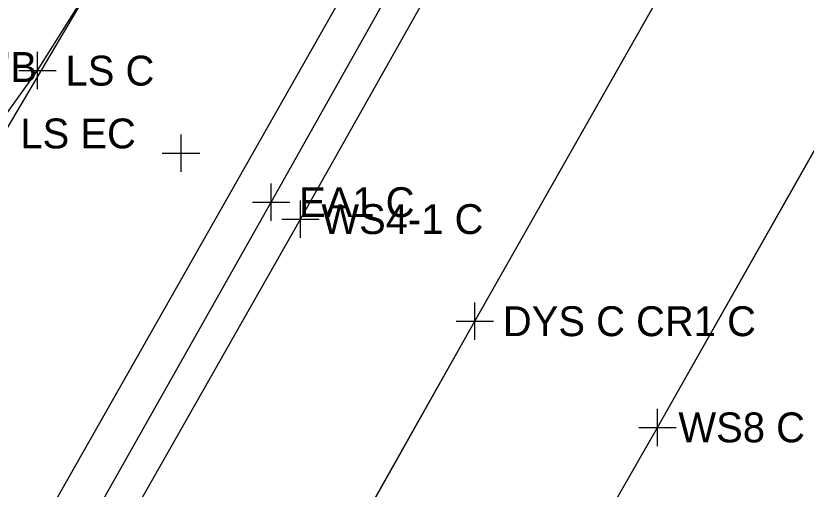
# Model space of a CAD drawing. Extents: x 1363693 to 1365209, y 422201 to 424153.
# Drawn here: x 1364063.69 to 1364106.01, y 422743.08 to 422768.44 of the extents above; entities that cross this region are included whole.
import ezdxf

# ---------------------------------------------------------------- set-up
doc = ezdxf.new("R2010")
doc.units = 0
for name, color, linetype in [('O-ALGN-BASELINE-WERK-CL-RW', 7, 'Continuous'), ('OWNERS', 7, 'Continuous'), ('PM_X_Channelizing_Line', 7, 'Continuous'), ('PM_X_CL_Double_Solid', 7, 'Continuous'), ('PM_X_Edge_Line', 7, 'Continuous'), ('SV_X_Original_Ground', 7, 'Continuous'), ('SV_X_Random_Point', 7, 'Continuous'), ('SV_X_Shot_Marker', 7, 'Continuous'), ('UT_X_FO', 7, 'Continuous'), ('UT_X_Gas', 7, 'Continuous'), ('VG_X_Flower_Bed', 7, 'Continuous'), ('VG_X_Text', 7, 'Continuous')]:
    doc.layers.add(name, color=color, linetype=linetype)

msp = doc.modelspace()

# ---------------------------------------------------------------- linework, layer by layer
at = {"layer": 'O-ALGN-BASELINE-WERK-CL-RW'}
for points in [[(1364063.861, 422708.444), (1364075.973, 422730.252), (1364088.269, 422752.078), (1364100.636, 422773.911), (1364112.961, 422795.674), (1364125.29, 422817.23)], [(1364073.278, 422703.065), (1364085.603, 422724.652), (1364098.051, 422746.39), (1364110.44, 422768.276), (1364122.785, 422790.021), (1364135.008, 422811.616)]]:
    msp.add_lwpolyline(points, dxfattribs=at)
at = {"layer": 'OWNERS'}
msp.add_lwpolyline([(1364052.728, 422714.955), (1364065.039, 422736.632), (1364077.353, 422758.456), (1364089.632, 422780.271), (1364102.08, 422801.911)], dxfattribs=at)
at = {"layer": 'PM_X_Channelizing_Line'}
for p, q in [((1364078.931, 422757.548), (1364091.221, 422779.339)), ((1364088.269, 422752.078), (1364100.636, 422773.911)), ((1364098.051, 422746.39), (1364110.44, 422768.276)), ((1364098.051, 422746.39), (1364110.44, 422768.276)), ((1364066.522, 422735.694), (1364078.931, 422757.548)), ((1364075.973, 422730.252), (1364088.269, 422752.078)), ((1364085.603, 422724.652), (1364098.051, 422746.39)), ((1364085.603, 422724.652), (1364098.051, 422746.39))]:
    msp.add_line(p, q, dxfattribs=at)
at = {"layer": 'PM_X_CL_Double_Solid'}
for p, q in [((1364088.269, 422752.078), (1364100.636, 422773.911)), ((1364075.973, 422730.252), (1364088.269, 422752.078))]:
    msp.add_line(p, q, dxfattribs=at)
at = {"layer": 'PM_X_Edge_Line'}
for p, q in [((1364078.931, 422757.548), (1364091.221, 422779.339)), ((1364066.522, 422735.694), (1364078.931, 422757.548))]:
    msp.add_line(p, q, dxfattribs=at)
at = {"layer": 'SV_X_Original_Ground'}
for p, q in [((1364072.532, 422760.084), (1364072.532, 422762.084)), ((1364071.532, 422761.084), (1364073.532, 422761.084)), ((1364078.931, 422756.548), (1364078.931, 422758.548)), ((1364077.931, 422757.548), (1364079.931, 422757.548)), ((1364088.269, 422751.078), (1364088.269, 422753.078)), ((1364087.269, 422752.078), (1364089.269, 422752.078)), ((1364098.051, 422745.39), (1364098.051, 422747.39)), ((1364097.051, 422746.39), (1364099.051, 422746.39))]:
    msp.add_line(p, q, dxfattribs=at)
at = {"layer": 'SV_X_Random_Point'}
for p, q in [((1364064.848, 422764.503), (1364064.848, 422766.503)), ((1364063.848, 422765.503), (1364065.848, 422765.503))]:
    msp.add_line(p, q, dxfattribs=at)
at = {"layer": 'SV_X_Shot_Marker'}
for p, q in [((1364077.353, 422757.456), (1364077.353, 422759.456)), ((1364076.353, 422758.456), (1364078.353, 422758.456))]:
    msp.add_line(p, q, dxfattribs=at)
at = {"layer": 'UT_X_FO'}
msp.add_lwpolyline([(1364198.41, 423083.145), (1364202.916, 423079.215), (1364206.614, 423072.625), (1364206.927, 423065.384), (1364205.607, 423052.889), (1364202.652, 423033.176), (1364193.585, 423006.537), (1364182.955, 422981.103), (1364130.325, 422876.058), (1364040.63, 422724.214)], dxfattribs=at)
at = {"layer": 'UT_X_Gas'}
msp.add_lwpolyline([(1364207.557, 423089.372), (1364211.518, 423072.856), (1364208.943, 423046.381), (1364201.649, 423012.485), (1364191.712, 422981.617), (1364181.14, 422953.292), (1364166.466, 422921.961), (1364127.708, 422851.525), (1364051.86, 422717.903)], dxfattribs=at)
at = {"layer": 'VG_X_Flower_Bed'}
for p, q in [((1364064.848, 422765.503), (1364078.24, 422786.815)), ((1364062.432, 422762.136), (1364064.848, 422765.503))]:
    msp.add_line(p, q, dxfattribs=at)

# ---------------------------------------------------------------- texts
at = {"layer": 'SV_X_Original_Ground'}
for s, p in [('WS4-1 C', (1364080.05, 422756.748)), ('DYS C CR1 C', (1364089.769, 422751.278)), ('WS8 C CR2 C', (1364099.17, 422745.59))]:
    msp.add_text(s, height=1.6, dxfattribs=at).set_placement(p)
at = {"layer": 'SV_X_Random_Point'}
for s, p in [('LS C', (1364066.348, 422764.703)), ('LS EC', (1364063.932, 422761.336))]:
    msp.add_text(s, height=1.6, dxfattribs=at).set_placement(p)
at = {"layer": 'SV_X_Shot_Marker'}
msp.add_text('EA1 C', height=1.6, dxfattribs=at).set_placement((1364078.853, 422757.656))
at = {"layer": 'VG_X_Text'}
msp.add_text("2'B", height=1.6, dxfattribs=at).set_placement((1364061.802, 422764.897))

doc.saveas('drawing.dxf')
